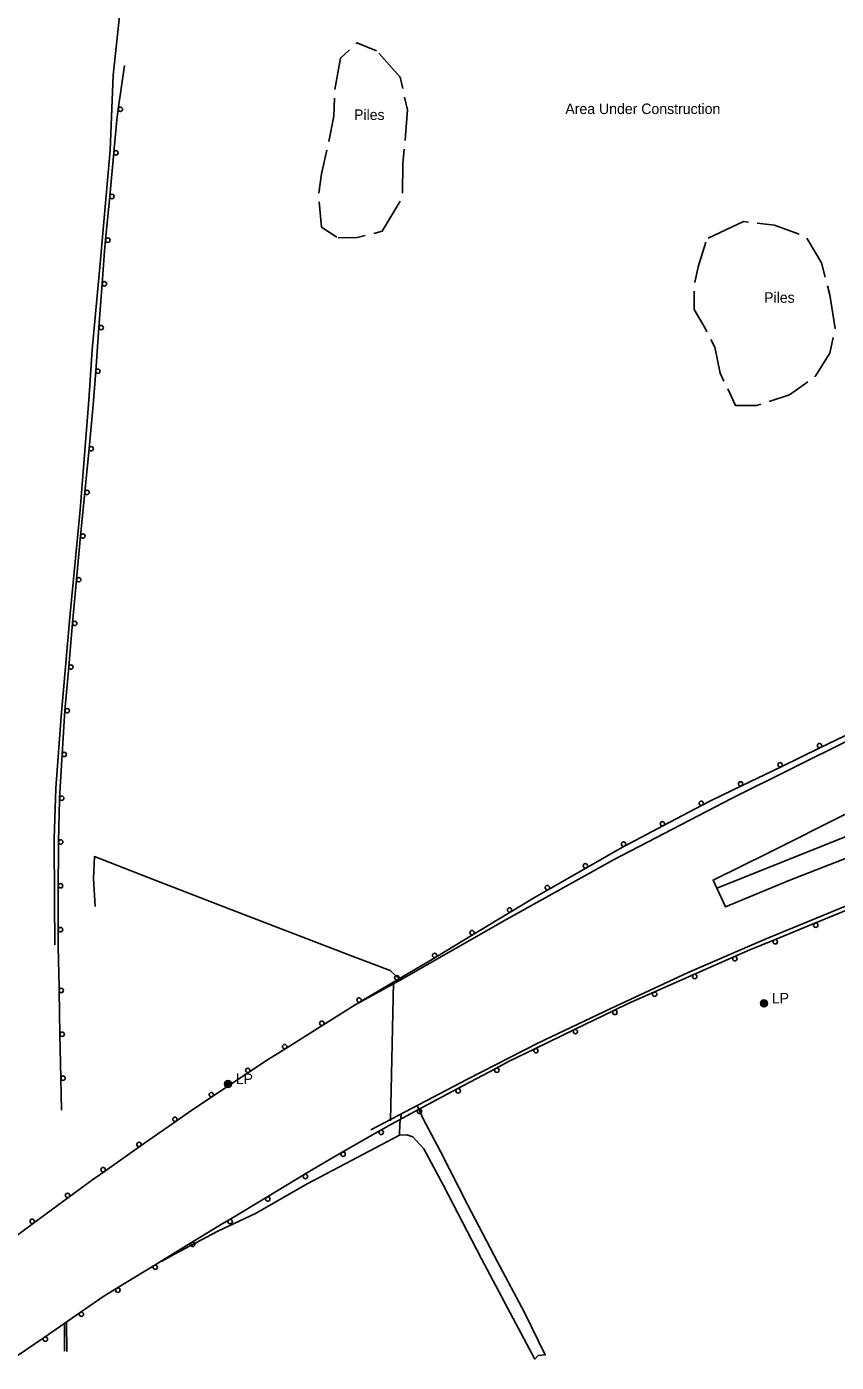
# Model space of a CAD drawing. Extents: x 2402803 to 2427059, y 6985292 to 6997652.
# Drawn here: x 2410720 to 2411089, y 6992037 to 6992646 of the extents above; entities that cross this region are included whole.
import ezdxf

# ---------------------------------------------------------------- set-up
doc = ezdxf.new("R2010")
doc.units = 0
for name, color, linetype in [('p_drainage conc drain', 7, 'Continuous'), ('p_drainage riprap', 7, 'Continuous'), ('p_dtm stock pile', 7, 'Continuous'), ('p_road - paved curb', 7, 'Continuous'), ('p_road bridge end', 7, 'Continuous'), ('p_road guard rails', 7, 'Continuous'), ('p_structure ruins', 7, 'Continuous'), ('p_utility manhole', 7, 'Continuous')]:
    doc.layers.add(name, color=color, linetype=linetype)

msp = doc.modelspace()

# ---------------------------------------------------------------- linework, layer by layer
at = {"layer": 'p_drainage conc drain'}
msp.add_lwpolyline([(2410889.81, 6992140.11), (2410893.12, 6992140.37), (2410895.88, 6992139.4), (2410900.92, 6992133.95), (2410909.85, 6992117.23), (2410927.2, 6992083.75), (2410941.66, 6992056.55), (2410951.53, 6992038.03), (2410953.09, 6992039.62), (2410956.26, 6992039.99), (2410946.72, 6992059.26), (2410934.44, 6992082.34), (2410921.02, 6992108.18), (2410908.44, 6992132.73), (2410900.57, 6992147.58), (2410897.91, 6992153.73)], dxfattribs=at)
at = {"layer": 'p_drainage riprap'}
for points in [[(2410890.06, 6992210.93), (2410885.63, 6992215.21), (2410867.51, 6992222.13), (2410812.96, 6992243.12), (2410775.2, 6992257.7), (2410750.77, 6992267.18), (2410750.39, 6992257.17), (2410751.07, 6992244.49)], [(2410890.72, 6992149.97), (2410890.02, 6992145.57), (2410889.81, 6992140.11), (2410867.95, 6992128.56), (2410847.68, 6992117.96), (2410824.12, 6992104.46), (2410807.02, 6992096.31), (2410787, 6992085.76), (2410781.49, 6992082.69), (2410781.41, 6992082.82)]]:
    msp.add_lwpolyline(points, dxfattribs=at)
at = {"layer": 'p_dtm stock pile'}
for points in [[(2410860.38, 6992617.11), (2410862.93, 6992631.32), (2410866.98, 6992635.13)], [(2410869.89, 6992637.88), (2410870.4, 6992638.36), (2410879.37, 6992634.65)], [(2410880.36, 6992633.58), (2410890.12, 6992622.73), (2410891.29, 6992617.49)], [(2410857.6, 6992593.35), (2410859.86, 6992604.88), (2410860.17, 6992613.12)], [(2410892.15, 6992613.58), (2410893.45, 6992607.75), (2410892.55, 6992596.09), (2410892.33, 6992593.78)], [(2410853.11, 6992569.81), (2410854.21, 6992578.62), (2410856.75, 6992589.44)], [(2410891.96, 6992589.8), (2410891.34, 6992583.12), (2410891.12, 6992569.83)], [(2410861.32, 6992549.68), (2410854.33, 6992554.22), (2410853.21, 6992565.83)], [(2410890.15, 6992566.09), (2410881.93, 6992552.36), (2410878.06, 6992551.4)], [(2411030.57, 6992549.31), (2411046.62, 6992556.85), (2411048.87, 6992556.59)], [(2411052.84, 6992556.13), (2411060.75, 6992555.21), (2411072.04, 6992551.04)], [(2410874.18, 6992550.43), (2410870.44, 6992549.5), (2410861.87, 6992549.44)], [(2411075.5, 6992549.3), (2411082.22, 6992537.93), (2411083.91, 6992531.38)], [(2411024.41, 6992529), (2411025.88, 6992536.15), (2411029.47, 6992547.47)], [(2411029.93, 6992506.57), (2411029.27, 6992507.89), (2411024.15, 6992516.71), (2411024.13, 6992525.03)], [(2411084.9, 6992527.51), (2411085.97, 6992523.36), (2411088.34, 6992508), (2411088.31, 6992507.83)], [(2411037.7, 6992484.07), (2411036.01, 6992487.64), (2411033.48, 6992499.48), (2411031.72, 6992502.99)], [(2411087.5, 6992503.92), (2411086.03, 6992496.76), (2411079.27, 6992486.09), (2411079.22, 6992486.05)], [(2411075.96, 6992483.73), (2411067.6, 6992477.76), (2411058.35, 6992474.78)], [(2411054.55, 6992473.56), (2411052.48, 6992472.89), (2411042.94, 6992472.96), (2411039.4, 6992480.45)]]:
    msp.add_lwpolyline(points, dxfattribs=at)
at = {"layer": 'p_road - paved curb'}
for points in [[(2410779.61, 6992824.88), (2410774.41, 6992772.43), (2410769.03, 6992724.05), (2410764.48, 6992671.9), (2410759.33, 6992623.63), (2410757.88, 6992589.4), (2410753.33, 6992537.66), (2410749.77, 6992498.36), (2410748.18, 6992475.31)], [(2410748.18, 6992475.31), (2410744.22, 6992425.41), (2410739.49, 6992376.45), (2410735.63, 6992331.06), (2410733.13, 6992298.44), (2410732.35, 6992275.25), (2410732.53, 6992247.18), (2410732.71, 6992227)], [(2411034.49, 6992252.73), (2411099.42, 6992278.86), (2411139.69, 6992293.76), (2411199.17, 6992314.16), (2411246.56, 6992328.99), (2411292.79, 6992341.81), (2411334.42, 6992350.97), (2411389.77, 6992363.22), (2411452.2, 6992375.7), (2411496.59, 6992383.37), (2411554.01, 6992392.4), (2411614.69, 6992398.92), (2411676.01, 6992403.47), (2411739, 6992405.53)], [(2410871.24, 6992200.46), (2410889.78, 6992210.77), (2410939.11, 6992238.81), (2410987.4, 6992265.72), (2411041.12, 6992293.77), (2411095.77, 6992320.86)], [(2411093.69, 6992286.79), (2411058.02, 6992268.91), (2411032.76, 6992256.52), (2411038.37, 6992244.24), (2411067.79, 6992256.4), (2411094.63, 6992266.97)], [(2411095.73, 6992245.69), (2411056.14, 6992229.43), (2411021.46, 6992214.31), (2410986.17, 6992197.97), (2410952.86, 6992182.15), (2410920.77, 6992165.66), (2410892.34, 6992150.82), (2410876.7, 6992142.61)]]:
    msp.add_lwpolyline(points, dxfattribs=at)
at = {"layer": 'p_road bridge end'}
msp.add_lwpolyline([(2410885.75, 6992146.63), (2410887.02, 6992209.95)], dxfattribs=at)
at = {"layer": 'p_road guard rails'}
for p, q in [((2410764.4, 6992627.93), (2410761.62, 6992608.14)), ((2410759.54, 6992588.25), (2410757.71, 6992568.34)), ((2410757.71, 6992568.34), (2410755.87, 6992548.42)), ((2410754.29, 6992528.49), (2410752.82, 6992508.54)), ((2410752.82, 6992508.54), (2410751.34, 6992488.6)), ((2410751.34, 6992488.6), (2410750.2, 6992473.2)), ((2410750.2, 6992473.2), (2410748.29, 6992453.29)), ((2410748.29, 6992453.29), (2410746.37, 6992433.39)), ((2410744.47, 6992413.48), (2410742.63, 6992393.56)), ((2410742.63, 6992393.56), (2410740.78, 6992373.65)), ((2410739.05, 6992353.72), (2410737.33, 6992333.8)), ((2411081.71, 6992316.9), (2411096.64, 6992324.13)), ((2411063.72, 6992308.18), (2411081.71, 6992316.9)), ((2410736.02, 6992313.84), (2410734.85, 6992293.88)), ((2411045.73, 6992299.47), (2411063.72, 6992308.18)), ((2411010.11, 6992281.31), (2411027.8, 6992290.63)), ((2410992.41, 6992271.99), (2411010.11, 6992281.31)), ((2410957.68, 6992252.19), (2410975.04, 6992262.11)), ((2410734.3, 6992253.88), (2410734.28, 6992233.88)), ((2411097.7, 6992244.37), (2411079.19, 6992236.82)), ((2410923.4, 6992231.65), (2410940.49, 6992242)), ((2410734.28, 6992233.88), (2410734.27, 6992226.13)), ((2410906.31, 6992221.29), (2410923.4, 6992231.65)), ((2411079.19, 6992236.82), (2411060.69, 6992229.28)), ((2411042.27, 6992221.51), (2411023.99, 6992213.43)), ((2411023.99, 6992213.43), (2411005.71, 6992205.34)), ((2410871.9, 6992200.93), (2410889.11, 6992211.1)), ((2410734.64, 6992206.13), (2410735.04, 6992186.14)), ((2410987.54, 6992197.02), (2410969.56, 6992188.29)), ((2410838, 6992179.72), (2410854.93, 6992190.36)), ((2410969.56, 6992188.29), (2410951.57, 6992179.57)), ((2410933.7, 6992170.63), (2410916.07, 6992161.26)), ((2410735.45, 6992166.14), (2410735.75, 6992151.58)), ((2410804.55, 6992157.82), (2410821.2, 6992168.87)), ((2410771.65, 6992135.1), (2410788.02, 6992146.58)), ((2410880.97, 6992142.27), (2410863.62, 6992132.34)), ((2410755.29, 6992123.61), (2410771.65, 6992135.1)), ((2410846.41, 6992122.16), (2410829.27, 6992111.87)), ((2410722.98, 6992100.05), (2410739.09, 6992111.9)), ((2410829.27, 6992111.87), (2410812.12, 6992101.59)), ((2410706.87, 6992088.21), (2410722.98, 6992100.05)), ((2410795.04, 6992091.18), (2410777.98, 6992080.75)), ((2410777.98, 6992080.75), (2410760.92, 6992070.33)), ((2410744.26, 6992059.29), (2410727.8, 6992047.94)), ((2410737.97, 6992054.82), (2410738.11, 6992041.51)), ((2410727.8, 6992047.94), (2410711.35, 6992036.58))]:
    msp.add_line(p, q, dxfattribs=at)
for points in [[(2410761.62, 6992608.14), (2410760.92, 6992603.14), (2410759.54, 6992588.25)], [(2410755.87, 6992548.42), (2410755.39, 6992543.27), (2410754.29, 6992528.49)], [(2410746.37, 6992433.39), (2410744.9, 6992418.09), (2410744.47, 6992413.48)], [(2410740.78, 6992373.65), (2410740.63, 6992372.02), (2410739.05, 6992353.72)], [(2410737.33, 6992333.8), (2410736.91, 6992328.93), (2410736.02, 6992313.84)], [(2411027.8, 6992290.63), (2411031.52, 6992292.59), (2411045.73, 6992299.47)], [(2410734.85, 6992293.88), (2410734.81, 6992293.26), (2410734.41, 6992273.88)], [(2410734.41, 6992273.88), (2410734.32, 6992269.27), (2410734.3, 6992253.88)], [(2410975.04, 6992262.11), (2410991.44, 6992271.48), (2410992.41, 6992271.99)], [(2410940.49, 6992242), (2410951.31, 6992248.55), (2410957.68, 6992252.19)], [(2410734.27, 6992226.13), (2410734.61, 6992207.49), (2410734.64, 6992206.13)], [(2411060.69, 6992229.28), (2411049.54, 6992224.73), (2411042.27, 6992221.51)], [(2410889.11, 6992211.1), (2410903.28, 6992219.46), (2410906.31, 6992221.29)], [(2410854.93, 6992190.36), (2410869.67, 6992199.62), (2410871.9, 6992200.93)], [(2411005.71, 6992205.34), (2410994.05, 6992200.18), (2410987.54, 6992197.02)], [(2410735.04, 6992186.14), (2410735.17, 6992179.54), (2410735.45, 6992166.14)], [(2410821.2, 6992168.87), (2410829.71, 6992174.51), (2410838, 6992179.72)], [(2410951.57, 6992179.57), (2410939.54, 6992173.73), (2410933.7, 6992170.63)], [(2410916.07, 6992161.26), (2410904.99, 6992155.38), (2410898.46, 6992151.88)], [(2410788.02, 6992146.58), (2410795.15, 6992151.59), (2410804.55, 6992157.82)], [(2410898.46, 6992151.88), (2410887.5, 6992146.01), (2410880.97, 6992142.27)], [(2410863.62, 6992132.34), (2410858.91, 6992129.65), (2410846.41, 6992122.16)], [(2410739.09, 6992111.9), (2410749.46, 6992119.52), (2410755.29, 6992123.61)], [(2410812.12, 6992101.59), (2410809.72, 6992100.15), (2410795.04, 6992091.18)], [(2410760.92, 6992070.33), (2410755.1, 6992066.77), (2410744.26, 6992059.29)], [(2410737.18, 6992053.86), (2410737.15, 6992048.19), (2410737.1, 6992041.58)]]:
    msp.add_lwpolyline(points, dxfattribs=at)
for centre in [(2410762.61, 6992608), (2410760.54, 6992588.16), (2410758.7, 6992568.24), (2410756.86, 6992548.33), (2410755.29, 6992528.41), (2410753.82, 6992508.47), (2410752.34, 6992488.53), (2410749.28, 6992453.2), (2410747.37, 6992433.29), (2410745.47, 6992413.38), (2410743.62, 6992393.47), (2410741.78, 6992373.56), (2410740.05, 6992353.64), (2410738.33, 6992333.71), (2411081.27, 6992317.8), (2410737.02, 6992313.78), (2411063.28, 6992309.08), (2411045.29, 6992300.37), (2410735.84, 6992293.82), (2411027.34, 6992291.52), (2411009.64, 6992282.2), (2410735.41, 6992273.86), (2410991.95, 6992272.88), (2410974.54, 6992262.98), (2410735.3, 6992253.88), (2410957.19, 6992253.06), (2410939.98, 6992242.85), (2410735.28, 6992233.88), (2410922.88, 6992232.5), (2411079.57, 6992235.9), (2411061.07, 6992228.35), (2410905.79, 6992222.15), (2411042.68, 6992220.6), (2411024.4, 6992212.51), (2410735.64, 6992206.15), (2410888.6, 6992211.96), (2410871.39, 6992201.8), (2411006.12, 6992204.43), (2410987.98, 6992196.12), (2410854.4, 6992191.2), (2410736.04, 6992186.16), (2410969.99, 6992187.39), (2410837.46, 6992180.56), (2410952.01, 6992178.67), (2410820.65, 6992169.7), (2410934.17, 6992169.75), (2410736.45, 6992166.16), (2410803.99, 6992158.66), (2410916.54, 6992160.38), (2410787.44, 6992147.4), (2410898.93, 6992151), (2410881.47, 6992141.41), (2410771.08, 6992135.92), (2410864.11, 6992131.48), (2410754.72, 6992124.43), (2410846.93, 6992121.3), (2410738.5, 6992112.7), (2410829.78, 6992111.01), (2410722.39, 6992100.86), (2410812.63, 6992100.73), (2410795.57, 6992090.33), (2410778.5, 6992079.9), (2410761.44, 6992069.47), (2410744.83, 6992058.47), (2410728.37, 6992047.11)]:
    msp.add_circle(centre, 1, dxfattribs=at)
at = {"layer": 'p_utility manhole'}
for centre, radius in [((2411055.93, 6992200.25), 1.6), ((2411055.93, 6992200.25), 1.3), ((2411055.93, 6992200.25), 1), ((2411055.93, 6992200.25), 0.539), ((2411055.93, 6992200.25), 0.192), ((2410811.61, 6992163.49), 1.6), ((2410811.61, 6992163.49), 1.3), ((2410811.61, 6992163.49), 1), ((2410811.61, 6992163.49), 0.539), ((2410811.61, 6992163.49), 0.192)]:
    msp.add_circle(centre, radius, dxfattribs=at)

# ---------------------------------------------------------------- texts
at = {"layer": 'p_dtm stock pile'}
for p in [(2410869.09, 6992603.13), (2411056.03, 6992519.76)]:
    msp.add_text('Piles', height=4.8, dxfattribs=at).set_placement(p)
at = {"layer": 'p_structure ruins'}
msp.add_text('Area Under Construction', height=4.8, dxfattribs=at).set_placement((2410965.41, 6992605.84))
at = {"layer": 'p_utility manhole'}
for p in [(2411055.93, 6992200.25), (2410811.61, 6992163.49)]:
    msp.add_text('  LP', height=4.8, dxfattribs=at).set_placement(p)

doc.saveas('drawing.dxf')
